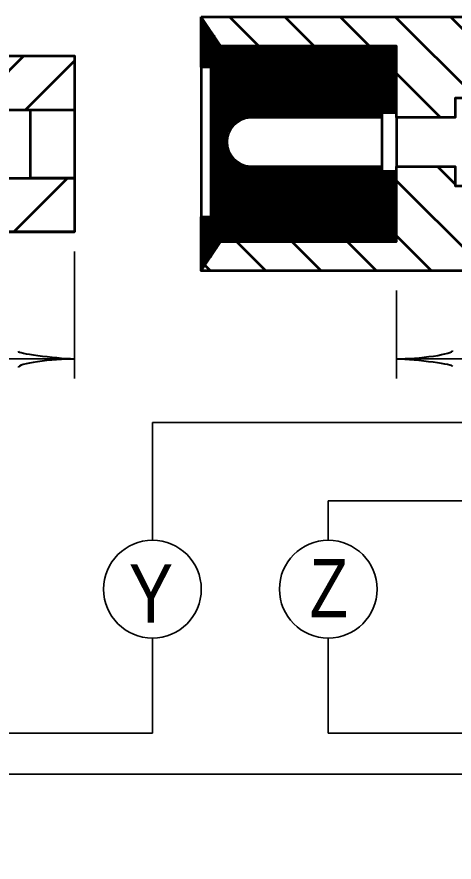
# Model space of a CAD drawing. Extents: x -1 to 679, y 0 to 440.
# Drawn here: x 342.46 to 364.84, y 108.8 to 152.05 of the extents above; entities that cross this region are included whole.
import ezdxf

# ---------------------------------------------------------------- set-up
doc = ezdxf.new("R2010")
doc.units = 0
doc.header["$LTSCALE"] = 0.8
doc.layers.add('1', color=7, linetype='Continuous', lineweight=53)

msp = doc.modelspace()

# ---------------------------------------------------------------- linework, layer by layer
at = {"layer": '1'}
for p, q in [((351.8991, 152.0358), (351.9053, 152.042)), ((352.0179, 151.8732), (351.8991, 151.9919)), ((351.8991, 151.8943), (351.9619, 151.9572)), ((351.8991, 151.7529), (352.0184, 151.8723)), ((352.3007, 151.4488), (351.8991, 151.8505)), ((354.8452, 150.5513), (353.3452, 152.0513)), ((357.6737, 150.5513), (356.1737, 152.0513)), ((360.5021, 150.5513), (359.0021, 152.0513)), ((365.9812, 147.9007), (361.8305, 152.0513)), ((368.8096, 147.9007), (364.6589, 152.0513)), ((351.8991, 151.6115), (352.075, 151.7874)), ((352.5836, 151.0246), (351.8991, 151.7091)), ((351.8991, 151.4701), (352.1316, 151.7026)), ((351.8991, 151.3287), (352.1882, 151.6178)), ((352.8664, 150.6003), (351.8991, 151.5677)), ((351.8991, 151.1873), (352.2448, 151.5328)), ((351.8991, 151.0458), (352.3013, 151.448)), ((356.4247, 146.9007), (351.8991, 151.4262)), ((351.8991, 150.9044), (352.3578, 151.3632)), ((356.2833, 146.9007), (351.8991, 151.2848)), ((351.8991, 150.7629), (352.4144, 151.2783)), ((351.8991, 150.6215), (352.471, 151.1934)), ((356.1418, 146.9007), (351.8991, 151.1434)), ((351.8991, 150.4801), (352.5276, 151.1086)), ((351.8991, 150.3387), (352.5842, 151.0238)), ((356.0004, 146.9007), (351.8991, 151.002)), ((351.8991, 150.1972), (352.6407, 150.9389)), ((355.859, 146.9007), (351.8991, 150.8606)), ((351.8991, 150.0558), (352.6972, 150.8541)), ((351.8991, 149.9144), (352.7538, 150.7692)), ((355.7176, 146.9007), (351.8991, 150.7192)), ((351.8991, 149.773), (352.8104, 150.6843)), ((351.8991, 149.6316), (352.867, 150.5995)), ((355.5762, 146.9007), (351.8991, 150.5778)), ((351.8991, 149.4902), (352.9602, 150.5513)), ((352.0323, 149.482), (353.1017, 150.5513)), ((352.1737, 149.482), (353.2431, 150.5513)), ((352.3152, 149.482), (353.3845, 150.5513)), ((352.3991, 149.4245), (353.5259, 150.5513)), ((352.3991, 149.2831), (353.6673, 150.5513)), ((352.3991, 149.1417), (353.8087, 150.5513)), ((352.3991, 149.0002), (353.9502, 150.5513)), ((352.3991, 148.8588), (354.0916, 150.5513)), ((352.3991, 148.7173), (354.2331, 150.5513)), ((352.3991, 148.5759), (354.3745, 150.5513)), ((352.3991, 148.4345), (354.5159, 150.5513)), ((352.3991, 148.2931), (354.6573, 150.5513)), ((352.3991, 148.1517), (354.7987, 150.5513)), ((352.3991, 148.0102), (354.9402, 150.5513)), ((352.3991, 147.8688), (355.0816, 150.5513)), ((352.3991, 147.7274), (355.223, 150.5513)), ((352.3991, 147.586), (355.3644, 150.5513)), ((352.3991, 147.4446), (355.5058, 150.5513)), ((352.3991, 147.3032), (355.6472, 150.5513)), ((352.3991, 147.1617), (355.7887, 150.5513)), ((352.3991, 147.0203), (355.9301, 150.5513)), ((352.3991, 146.8789), (356.0715, 150.5513)), ((352.3991, 146.7375), (356.2129, 150.5513)), ((352.3991, 146.5961), (356.3543, 150.5513)), ((352.3991, 146.4547), (356.4957, 150.5513)), ((352.3991, 146.3132), (356.6372, 150.5513)), ((352.3991, 146.1718), (356.7787, 150.5513)), ((352.3991, 146.0303), (356.9201, 150.5513)), ((352.3991, 145.8889), (357.0615, 150.5513)), ((352.3991, 145.7475), (357.2029, 150.5513)), ((352.3991, 145.6061), (357.3443, 150.5513)), ((352.3991, 145.4647), (357.4857, 150.5513)), ((356.5661, 146.9007), (352.9154, 150.5513)), ((356.7075, 146.9007), (353.0568, 150.5513)), ((356.8489, 146.9007), (353.1982, 150.5513)), ((356.9903, 146.9007), (353.3397, 150.5513)), ((357.1318, 146.9007), (353.4811, 150.5513)), ((357.2732, 146.9007), (353.6225, 150.5513)), ((357.4146, 146.9007), (353.7639, 150.5513)), ((353.7827, 146.7069), (357.6272, 150.5513)), ((357.556, 146.9007), (353.9053, 150.5513)), ((357.6974, 146.9007), (354.0467, 150.5513)), ((354.0513, 146.8341), (357.7686, 150.5513)), ((357.8389, 146.9007), (354.1882, 150.5513)), ((354.2412, 146.8826), (357.91, 150.5513)), ((357.9803, 146.9007), (354.3297, 150.5513)), ((354.4008, 146.9007), (358.0514, 150.5513)), ((358.1217, 146.9007), (354.4711, 150.5513)), ((354.5422, 146.9007), (358.1928, 150.5513)), ((358.2632, 146.9007), (354.6125, 150.5513)), ((354.6836, 146.9007), (358.3342, 150.5513)), ((358.4046, 146.9007), (354.7539, 150.5513)), ((354.825, 146.9007), (358.4757, 150.5513)), ((358.546, 146.9007), (354.8953, 150.5513)), ((354.9664, 146.9007), (358.6171, 150.5513)), ((358.6874, 146.9007), (355.0367, 150.5513)), ((355.1078, 146.9007), (358.7585, 150.5513)), ((358.8288, 146.9007), (355.1782, 150.5513)), ((355.2492, 146.9007), (358.8999, 150.5513)), ((358.9702, 146.9007), (355.3196, 150.5513)), ((355.3907, 146.9007), (359.0413, 150.5513)), ((359.1117, 146.9007), (355.461, 150.5513)), ((355.5322, 146.9007), (359.1828, 150.5513)), ((359.2531, 146.9007), (355.6024, 150.5513)), ((355.6736, 146.9007), (359.3243, 150.5513)), ((359.3945, 146.9007), (355.7438, 150.5513)), ((355.815, 146.9007), (359.4657, 150.5513)), ((359.5359, 146.9007), (355.8852, 150.5513)), ((355.9564, 146.9007), (359.6071, 150.5513)), ((359.6773, 146.9007), (356.0267, 150.5513)), ((356.0978, 146.9007), (359.7485, 150.5513)), ((359.8187, 146.9007), (356.1681, 150.5513)), ((356.2392, 146.9007), (359.8899, 150.5513)), ((359.9602, 146.9007), (356.3095, 150.5513)), ((356.3807, 146.9007), (360.0313, 150.5513)), ((360.1016, 146.9007), (356.4509, 150.5513)), ((356.5221, 146.9007), (360.1728, 150.5513)), ((360.243, 146.9007), (356.5923, 150.5513)), ((356.6635, 146.9007), (360.3142, 150.5513)), ((360.3845, 146.9007), (356.7338, 150.5513)), ((356.8049, 146.9007), (360.4556, 150.5513)), ((360.5259, 146.9007), (356.8752, 150.5513)), ((356.9463, 146.9007), (360.597, 150.5513)), ((360.6673, 146.9007), (357.0167, 150.5513)), ((357.0877, 146.9007), (360.7384, 150.5513)), ((360.8087, 146.9007), (357.1581, 150.5513)), ((357.2292, 146.9007), (360.8798, 150.5513)), ((360.9502, 146.9007), (357.2995, 150.5513)), ((357.3706, 146.9007), (361.0213, 150.5513)), ((361.0916, 146.9007), (357.4409, 150.5513)), ((357.512, 146.9007), (361.1627, 150.5513)), ((361.1491, 146.9846), (357.5823, 150.5513)), ((357.6534, 146.9007), (361.3041, 150.5513)), ((361.1491, 147.126), (357.7237, 150.5513)), ((357.7948, 146.9007), (361.4455, 150.5513)), ((361.2658, 147.1507), (357.8652, 150.5513)), ((357.9362, 146.9007), (361.5869, 150.5513)), ((361.4072, 147.1507), (358.0066, 150.5513)), ((358.0777, 146.9007), (361.7284, 150.5513)), ((361.5487, 147.1507), (358.148, 150.5513)), ((358.2192, 146.9007), (361.8698, 150.5513)), ((361.6901, 147.1507), (358.2894, 150.5513)), ((361.8315, 147.1507), (358.4308, 150.5513)), ((361.8991, 147.2245), (358.5722, 150.5513)), ((361.8991, 147.3659), (358.7137, 150.5513)), ((361.8991, 147.5073), (358.8551, 150.5513)), ((361.8991, 147.6488), (358.9965, 150.5513)), ((361.8991, 147.7902), (359.138, 150.5513)), ((361.8991, 147.9317), (359.2794, 150.5513)), ((361.8991, 148.0731), (359.4208, 150.5513)), ((361.8991, 148.2145), (359.5623, 150.5513)), ((361.8991, 148.3559), (359.7037, 150.5513)), ((361.8991, 148.4973), (359.8451, 150.5513)), ((361.8991, 148.6387), (359.9865, 150.5513)), ((361.8991, 148.7802), (360.1279, 150.5513)), ((361.8991, 148.9216), (360.2693, 150.5513)), ((361.8991, 149.063), (360.4108, 150.5513)), ((361.8991, 149.2044), (360.5522, 150.5513)), ((361.8991, 149.3458), (360.6936, 150.5513)), ((361.8991, 149.4872), (360.835, 150.5513)), ((361.8991, 149.6287), (360.9764, 150.5513)), ((361.8991, 149.7701), (361.1178, 150.5513)), ((361.8991, 149.9115), (361.2593, 150.5513)), ((361.8991, 150.0529), (361.4007, 150.5513)), ((361.8991, 150.1943), (361.5421, 150.5513)), ((361.8991, 150.3358), (361.6836, 150.5513)), ((361.8991, 150.4772), (361.825, 150.5513)), ((355.4348, 146.9007), (351.8991, 150.4363)), ((355.2933, 146.9007), (351.8991, 150.2949)), ((355.1518, 146.9007), (351.8991, 150.1534)), ((358.3606, 146.9007), (361.8991, 150.4392)), ((358.502, 146.9007), (361.8991, 150.2978)), ((358.6434, 146.9007), (361.8991, 150.1563)), ((340.0669, 147.3013), (342.8169, 150.0513)), ((342.8953, 147.3013), (345.3991, 149.8051)), ((355.0104, 146.9007), (351.8991, 150.012)), ((352.2877, 149.482), (351.8991, 149.8706)), ((352.1463, 149.482), (351.8991, 149.7292)), ((358.7848, 146.9007), (361.8991, 150.0149)), ((358.9262, 146.9007), (361.8991, 149.8735)), ((359.0677, 146.9007), (361.8991, 149.7321)), ((352.0048, 149.482), (351.8991, 149.5877)), ((351.8991, 149.482), (351.8991, 141.8192)), ((354.869, 146.9007), (352.3991, 149.3706)), ((354.7276, 146.9007), (352.3991, 149.2292)), ((359.2091, 146.9007), (361.8991, 149.5907)), ((359.3505, 146.9007), (361.8991, 149.4493)), ((359.4919, 146.9007), (361.8991, 149.3078)), ((354.5862, 146.9007), (352.3991, 149.0877)), ((354.4447, 146.9007), (352.3991, 148.9463)), ((354.3117, 146.8922), (352.3991, 148.8049)), ((359.6333, 146.9007), (361.8991, 149.1664)), ((359.7747, 146.9007), (361.8991, 149.025)), ((359.9162, 146.9007), (361.8991, 148.8836)), ((364.1527, 146.9007), (361.8991, 149.1543)), ((354.1903, 146.8723), (352.3991, 148.6635)), ((354.0785, 146.8427), (352.3991, 148.5221)), ((353.9747, 146.8051), (352.3991, 148.3807)), ((360.0576, 146.9007), (361.8991, 148.7422)), ((360.199, 146.9007), (361.8991, 148.6008)), ((360.3404, 146.9007), (361.8991, 148.4593)), ((353.8777, 146.7606), (352.3991, 148.2392)), ((353.7873, 146.7096), (352.3991, 148.0978)), ((353.7043, 146.6513), (352.3991, 147.9564)), ((360.4818, 146.9007), (361.8991, 148.3179)), ((360.6233, 146.9007), (361.8991, 148.1764)), ((360.7647, 146.9007), (361.8991, 148.035)), ((353.6265, 146.5876), (352.3991, 147.815)), ((353.5539, 146.5187), (352.3991, 147.6736)), ((353.4865, 146.4447), (352.3991, 147.5322)), ((361.1562, 147.1507), (361.8991, 147.8936)), ((361.2976, 147.1507), (361.8991, 147.7522)), ((361.439, 147.1507), (361.8991, 147.6107)), ((335.1491, 147.3013), (345.3991, 147.3013)), ((353.4263, 146.3635), (352.3991, 147.3907)), ((353.3717, 146.2766), (352.3991, 147.2493)), ((353.3231, 146.1838), (352.3991, 147.1078)), ((360.9062, 146.9007), (361.1491, 147.1436)), ((361.5804, 147.1507), (361.8991, 147.4693)), ((361.7218, 147.1507), (361.8991, 147.3279)), ((361.8632, 147.1507), (361.8991, 147.1865)), ((353.2809, 146.0847), (352.3991, 146.9664)), ((353.246, 145.9781), (352.3991, 146.825)), ((353.2203, 145.8623), (352.3991, 146.6836)), ((361.0476, 146.9007), (361.1491, 147.0022)), ((361.1491, 146.9007), (361.1491, 144.4007)), ((361.8991, 146.9007), (361.8991, 144.4007)), ((353.2053, 145.7359), (352.3991, 146.5422)), ((353.2032, 145.5967), (352.3991, 146.4007)), ((352.3991, 145.3233), (353.3996, 146.3237)), ((353.2217, 145.4367), (352.3991, 146.2593)), ((353.2706, 145.2465), (352.3991, 146.1179)), ((352.3991, 145.1818), (353.2703, 146.0531)), ((353.4001, 144.9755), (352.3991, 145.9765)), ((352.3991, 145.0404), (353.2201, 145.8614)), ((357.6828, 140.5513), (352.3991, 145.8351)), ((352.3991, 144.899), (353.2042, 145.7041)), ((357.5414, 140.5513), (352.3991, 145.6937)), ((352.3991, 144.7576), (353.2063, 145.5648)), ((357.4, 140.5513), (352.3991, 145.5522)), ((352.3991, 144.6162), (353.2213, 145.4384)), ((357.2586, 140.5513), (352.3991, 145.4108)), ((352.3991, 144.4748), (353.2467, 145.3223)), ((357.1172, 140.5513), (352.3991, 145.2694)), ((352.3991, 144.3333), (353.2805, 145.2148)), ((356.9758, 140.5513), (352.3991, 145.128)), ((352.3991, 144.1919), (353.3232, 145.116)), ((352.3991, 144.0505), (353.3723, 145.0238)), ((356.8343, 140.5513), (352.3991, 144.9866)), ((352.3991, 143.9091), (353.4273, 144.9373)), ((352.3991, 143.7676), (353.4878, 144.8563)), ((356.6929, 140.5513), (352.3991, 144.8452)), ((352.3991, 143.6262), (353.5541, 144.7812)), ((352.3991, 143.4847), (353.6272, 144.7129)), ((356.5514, 140.5513), (352.3991, 144.7037)), ((352.3991, 143.3433), (353.7054, 144.6497)), ((352.3991, 143.2019), (353.789, 144.5918)), ((356.41, 140.5513), (352.3991, 144.5623)), ((352.3991, 143.0605), (353.8782, 144.5397)), ((352.3991, 142.9191), (353.9753, 144.4953)), ((352.3991, 142.7777), (354.0796, 144.4582)), ((357.8243, 140.5513), (353.7763, 144.5993)), ((357.9657, 140.5513), (354.0484, 144.4686)), ((351.8991, 141.2877), (355.012, 144.4007)), ((351.8991, 141.1463), (355.1534, 144.4007)), ((351.8991, 141.0049), (355.2948, 144.4007)), ((351.8991, 140.8635), (355.4362, 144.4007)), ((351.8991, 140.722), (355.5777, 144.4007)), ((351.8991, 140.5806), (355.7192, 144.4007)), ((351.8991, 140.4392), (355.8606, 144.4007)), ((351.8991, 140.2978), (356.002, 144.4007)), ((351.8991, 140.1563), (356.1434, 144.4007)), ((351.8991, 140.0149), (356.2848, 144.4007)), ((351.8991, 139.8735), (356.4262, 144.4007)), ((351.8991, 139.7321), (356.5677, 144.4007)), ((351.8991, 139.5907), (356.7091, 144.4007)), ((352.3991, 142.6362), (354.1917, 144.4288)), ((356.2686, 140.5513), (352.3991, 144.4208)), ((352.3991, 142.4948), (354.3133, 144.4091)), ((352.3991, 142.3534), (354.4463, 144.4007)), ((352.3991, 142.212), (354.5877, 144.4007)), ((352.3991, 142.0706), (354.7292, 144.4007)), ((352.3991, 141.9292), (354.8706, 144.4007)), ((356.1272, 140.5513), (352.3991, 144.2794)), ((355.9857, 140.5513), (352.3991, 144.138)), ((353.0012, 140.5513), (356.8505, 144.4007)), ((353.1426, 140.5513), (356.9919, 144.4007)), ((353.284, 140.5513), (357.1333, 144.4007)), ((353.4254, 140.5513), (357.2747, 144.4007)), ((353.5668, 140.5513), (357.4162, 144.4007)), ((353.7082, 140.5513), (357.5576, 144.4007)), ((353.8497, 140.5513), (357.699, 144.4007)), ((353.9911, 140.5513), (357.8404, 144.4007)), ((354.1325, 140.5513), (357.9818, 144.4007)), ((358.1071, 140.5513), (354.2404, 144.418)), ((354.274, 140.5513), (358.1233, 144.4007)), ((358.2485, 140.5513), (354.3992, 144.4007)), ((354.4154, 140.5513), (358.2647, 144.4007)), ((358.3899, 140.5513), (354.5406, 144.4007)), ((354.5568, 140.5513), (358.4062, 144.4007)), ((358.5313, 140.5513), (354.682, 144.4007)), ((354.6982, 140.5513), (358.5476, 144.4007)), ((358.6728, 140.5513), (354.8234, 144.4007)), ((354.8397, 140.5513), (358.689, 144.4007)), ((358.8142, 140.5513), (354.9648, 144.4007)), ((354.9811, 140.5513), (358.8304, 144.4007)), ((358.9556, 140.5513), (355.1062, 144.4007)), ((355.1225, 140.5513), (358.9718, 144.4007)), ((359.0971, 140.5513), (355.2477, 144.4007)), ((355.2639, 140.5513), (359.1132, 144.4007)), ((359.2385, 140.5513), (355.3892, 144.4007)), ((355.4053, 140.5513), (359.2547, 144.4007)), ((359.3799, 140.5513), (355.5306, 144.4007)), ((355.5467, 140.5513), (359.3961, 144.4007)), ((359.5213, 140.5513), (355.672, 144.4007)), ((355.6882, 140.5513), (359.5375, 144.4007)), ((359.6627, 140.5513), (355.8134, 144.4007)), ((355.8296, 140.5513), (359.6789, 144.4007)), ((359.8042, 140.5513), (355.9548, 144.4007)), ((355.971, 140.5513), (359.8203, 144.4007)), ((359.9456, 140.5513), (356.0962, 144.4007)), ((356.1124, 140.5513), (359.9617, 144.4007)), ((360.087, 140.5513), (356.2377, 144.4007)), ((356.2538, 140.5513), (360.1032, 144.4007)), ((360.2284, 140.5513), (356.3791, 144.4007)), ((356.3952, 140.5513), (360.2446, 144.4007)), ((360.3698, 140.5513), (356.5205, 144.4007)), ((356.5367, 140.5513), (360.386, 144.4007)), ((360.5112, 140.5513), (356.6619, 144.4007)), ((356.6781, 140.5513), (360.5274, 144.4007)), ((360.6527, 140.5513), (356.8033, 144.4007)), ((356.8196, 140.5513), (360.6689, 144.4007)), ((360.7941, 140.5513), (356.9447, 144.4007)), ((356.961, 140.5513), (360.8103, 144.4007)), ((360.9355, 140.5513), (357.0862, 144.4007)), ((357.1024, 140.5513), (360.9518, 144.4007)), ((361.0769, 140.5513), (357.2276, 144.4007)), ((357.2438, 140.5513), (361.0932, 144.4007)), ((361.2183, 140.5513), (357.369, 144.4007)), ((357.3852, 140.5513), (361.1491, 144.3152)), ((361.3597, 140.5513), (357.5104, 144.4007)), ((357.5267, 140.5513), (361.1491, 144.1737)), ((361.5012, 140.5513), (357.6518, 144.4007)), ((357.6681, 140.5513), (361.2674, 144.1507)), ((361.6427, 140.5513), (357.7933, 144.4007)), ((357.8095, 140.5513), (361.4088, 144.1507)), ((361.7841, 140.5513), (357.9348, 144.4007)), ((357.9509, 140.5513), (361.5503, 144.1507)), ((361.8991, 140.5778), (358.0762, 144.4007)), ((358.0923, 140.5513), (361.6917, 144.1507)), ((361.8991, 140.7192), (358.2176, 144.4007)), ((358.2337, 140.5513), (361.8331, 144.1507)), ((361.8991, 140.8606), (358.359, 144.4007)), ((358.3752, 140.5513), (361.8991, 144.0752)), ((361.8991, 141.002), (358.5004, 144.4007)), ((361.8991, 141.1434), (358.6418, 144.4007)), ((361.8991, 141.2848), (358.7833, 144.4007)), ((361.8991, 141.4262), (358.9247, 144.4007)), ((361.8991, 141.5677), (359.0661, 144.4007)), ((361.8991, 141.7091), (359.2075, 144.4007)), ((361.8991, 141.8505), (359.3489, 144.4007)), ((361.8991, 141.9919), (359.4903, 144.4007)), ((361.8991, 142.1333), (359.6318, 144.4007)), ((361.8991, 142.2747), (359.7732, 144.4007)), ((361.8991, 142.4162), (359.9146, 144.4007)), ((361.8991, 142.5576), (360.056, 144.4007)), ((361.8991, 142.699), (360.1974, 144.4007)), ((361.8991, 142.8405), (360.3389, 144.4007)), ((361.8991, 142.9819), (360.4803, 144.4007)), ((361.8991, 143.1233), (360.6217, 144.4007)), ((361.8991, 143.2647), (360.7632, 144.4007)), ((361.1491, 144.1562), (360.9046, 144.4007)), ((361.1491, 144.2976), (361.046, 144.4007)), ((361.8991, 143.4062), (361.1546, 144.1507)), ((361.8991, 143.5476), (361.296, 144.1507)), ((361.8991, 143.689), (361.4374, 144.1507)), ((361.8991, 143.8304), (361.5788, 144.1507)), ((361.8991, 143.9718), (361.7202, 144.1507)), ((361.8991, 144.1132), (361.8617, 144.1507)), ((364.8991, 143.4993), (363.9977, 144.4007)), ((335.1491, 143.8013), (345.3991, 143.8013)), ((342.3023, 141.0513), (345.0523, 143.8013)), ((355.8443, 140.5513), (352.3991, 143.9966)), ((355.7029, 140.5513), (352.3991, 143.8552)), ((355.5615, 140.5513), (352.3991, 143.7138)), ((358.5166, 140.5513), (361.8991, 143.9338)), ((358.658, 140.5513), (361.8991, 143.7924)), ((358.7994, 140.5513), (361.8991, 143.651)), ((366.5187, 139.0513), (361.8991, 143.6709)), ((355.4201, 140.5513), (352.3991, 143.5723)), ((355.2787, 140.5513), (352.3991, 143.4309)), ((355.1372, 140.5513), (352.3991, 143.2895)), ((358.9408, 140.5513), (361.8991, 143.5096)), ((359.0822, 140.5513), (361.8991, 143.3682)), ((359.2237, 140.5513), (361.8991, 143.2267)), ((354.9958, 140.5513), (352.3991, 143.1481)), ((354.8544, 140.5513), (352.3991, 143.0067)), ((354.713, 140.5513), (352.3991, 142.8653)), ((359.3652, 140.5513), (361.8991, 143.0853)), ((359.5066, 140.5513), (361.8991, 142.9438)), ((359.648, 140.5513), (361.8991, 142.8024)), ((354.5716, 140.5513), (352.3991, 142.7238)), ((354.4302, 140.5513), (352.3991, 142.5824)), ((354.2887, 140.5513), (352.3991, 142.441)), ((354.1473, 140.5513), (352.3991, 142.2996)), ((359.7894, 140.5513), (361.8991, 142.661)), ((359.9308, 140.5513), (361.8991, 142.5196)), ((360.0722, 140.5513), (361.8991, 142.3782)), ((354.0058, 140.5513), (352.3991, 142.1581)), ((353.8644, 140.5513), (352.3991, 142.0167)), ((353.723, 140.5513), (352.3991, 141.8752)), ((360.2137, 140.5513), (361.8991, 142.2368)), ((360.3551, 140.5513), (361.8991, 142.0953)), ((360.4965, 140.5513), (361.8991, 141.9539)), ((351.8991, 141.712), (352.0063, 141.8192)), ((351.8991, 141.5706), (352.1477, 141.8192)), ((351.8991, 141.4292), (352.2892, 141.8192)), ((353.1573, 140.5513), (351.8991, 141.8096)), ((353.0159, 140.5513), (351.8991, 141.6682)), ((352.8893, 140.5366), (351.8991, 141.5267)), ((353.2987, 140.5513), (352.0308, 141.8192)), ((353.4402, 140.5513), (352.1722, 141.8192)), ((353.5816, 140.5513), (352.3137, 141.8192)), ((360.6379, 140.5513), (361.8991, 141.8125)), ((360.7793, 140.5513), (361.8991, 141.6711)), ((360.9207, 140.5513), (361.8991, 141.5297)), ((335.3991, 141.0513), (345.3991, 141.0513)), ((352.8327, 140.4518), (351.8991, 141.3853)), ((352.7761, 140.3669), (351.8991, 141.2439)), ((352.7196, 140.282), (351.8991, 141.1025)), ((361.0622, 140.5513), (361.8991, 141.3882)), ((361.2036, 140.5513), (361.8991, 141.2468)), ((361.345, 140.5513), (361.8991, 141.1054)), ((352.663, 140.1972), (351.8991, 140.9611)), ((352.6064, 140.1123), (351.8991, 140.8197)), ((352.5498, 140.0275), (351.8991, 140.6782)), ((361.4864, 140.5513), (361.8991, 140.964)), ((361.6278, 140.5513), (361.8991, 140.8226)), ((361.7693, 140.5513), (361.8991, 140.6811)), ((363.6902, 139.0513), (361.8991, 140.8424)), ((352.4932, 139.9426), (351.8991, 140.5368)), ((352.4367, 139.8577), (351.8991, 140.3954)), ((352.3802, 139.7729), (351.8991, 140.254)), ((351.8991, 139.4493), (352.6949, 140.2451)), ((355.2049, 139.0513), (353.7049, 140.5513)), ((358.0333, 139.0513), (356.5333, 140.5513)), ((360.8617, 139.0513), (359.3617, 140.5513)), ((352.3236, 139.6881), (351.8991, 140.1125)), ((352.267, 139.6032), (351.8991, 139.9711)), ((352.2104, 139.5183), (351.8991, 139.8297)), ((351.8991, 139.3078), (352.4121, 139.8208)), ((352.1538, 139.4335), (351.8991, 139.6882)), ((352.0972, 139.3487), (351.8991, 139.5468)), ((352.0408, 139.2638), (351.8991, 139.4054)), ((351.8991, 139.1664), (352.1293, 139.3966)), ((352.3765, 139.0513), (352.0901, 139.3377)), ((351.9842, 139.1789), (351.8991, 139.264)), ((351.9276, 139.0941), (351.8991, 139.1226))]:
    msp.add_line(p, q, dxfattribs=at)
at = {"layer": '1', "lineweight": 35}
for p, q in [((345.3991, 140.0513), (345.3991, 133.5513)), ((361.8991, 138.0513), (361.8991, 133.5513)), ((306.3991, 134.5513), (345.3991, 134.5513)), ((361.8991, 134.5513), (386.3991, 134.5513)), ((393.3991, 131.3013), (349.3991, 131.3013)), ((349.3991, 131.3013), (349.3991, 125.2666)), ((404.3991, 127.2931), (358.3991, 127.2931)), ((358.3991, 127.2931), (358.3991, 125.2666)), ((349.3991, 120.2666), (349.3991, 115.4007)), ((358.3991, 120.2666), (358.3991, 115.4007)), ((349.3991, 115.4007), (335.1377, 115.4007)), ((339.8991, 113.3013), (386.3738, 113.3013))]:
    msp.add_line(p, q, dxfattribs=at)
at = {"layer": '1'}
for points in [[(315.3991, 149.5513), (321.3991, 151.0513), (321.3991, 152.0513), (335.3991, 152.0513), (335.3991, 150.0513), (345.3991, 150.0513), (345.3991, 143.8013), (345.3991, 141.0513), (335.3991, 141.0513), (335.3991, 139.0513), (321.3991, 139.0513), (321.3991, 140.0513), (315.3991, 141.5513), (306.3991, 141.5513), (306.3991, 143.3013)], [(351.8991, 139.0513), (351.8991, 141.8192), (352.3991, 141.8192), (352.3991, 149.482), (351.8991, 149.482), (351.8991, 152.0513)], [(361.8991, 147.1507), (361.1491, 147.1507), (361.1491, 146.9007), (354.3991, 146.9007)], [(354.3991, 144.4007), (361.1491, 144.4007), (361.1491, 144.1507), (361.8991, 144.1507)]]:
    msp.add_lwpolyline(points, dxfattribs=at)
for points in [[(351.8991, 152.0513), (371.3991, 152.0513), (371.3991, 151.0513), (377.3991, 149.5513), (386.3991, 149.5513), (386.3991, 147.4007), (377.3991, 147.4007), (376.3991, 147.9007), (364.8991, 147.9007), (364.8991, 146.9007), (361.8991, 146.9007), (361.8991, 150.5513), (352.8991, 150.5513)], [(343.1491, 143.8013), (343.1491, 147.3013), (345.3991, 147.3013), (345.3991, 143.8013)], [(386.3991, 143.9007), (386.3991, 141.5513), (377.3991, 141.5513), (371.3991, 140.0513), (371.3991, 139.0513), (351.8991, 139.0513), (352.8991, 140.5513), (361.8991, 140.5513), (361.8991, 144.4007), (364.8991, 144.4007), (364.8991, 143.4007), (376.3991, 143.4007), (377.3991, 143.9007)]]:
    msp.add_lwpolyline(points, close=True, dxfattribs=at)
at = {"layer": '1', "lineweight": 35}
msp.add_lwpolyline([(358.3991, 115.4007), (392.8568, 115.4007), (392.8568, 108.8013)], dxfattribs=at)
for centre in [(349.3991, 122.7666), (358.3991, 122.7666)]:
    msp.add_circle(centre, 2.5, dxfattribs=at)
at = {"layer": '1'}
msp.add_arc((354.4532, 145.6507), 1.2512, 92.47907, 267.52093, dxfattribs=at)
at = {"layer": '1', "lineweight": 40}
for centre, major_axis, ratio, start_param, end_param in [((362.9903, 134.8276), (-1.7857, -0.1562), 0.122415, 0.8963533, 3.1415927), ((362.9903, 134.8276), (-1.7857, -0.1562), 0.122415, 0.8963533, 3.1415927), ((344.3079, 134.275), (1.7857, 0.1562), 0.122415, 0.8963533, 3.1415927), ((344.3079, 134.275), (1.7857, 0.1562), 0.122415, 0.8963533, 3.1415927), ((344.2786, 134.7629), (1.7565, -0.1757), 0.07063, 3.1407148, 5.41811), ((344.2786, 134.7629), (1.7565, -0.1757), 0.07063, 3.1407148, 5.41811), ((363.0196, 134.3397), (-1.7565, 0.1757), 0.07063, 3.1407148, 5.41811), ((363.0196, 134.3397), (-1.7565, 0.1757), 0.07063, 3.1407148, 5.41811)]:
    msp.add_ellipse(centre, major_axis=major_axis, ratio=ratio, start_param=start_param, end_param=end_param, dxfattribs=at)

# ---------------------------------------------------------------- texts
at = {"layer": '1'}
for s, width, p in [('Z', 0.8, (357.449, 121.3192)), ('Y', 0.85, (348.1827, 121.0453))]:
    msp.add_text(s, height=3, dxfattribs=dict(at, width=width)).set_placement(p)

doc.saveas('drawing.dxf')
